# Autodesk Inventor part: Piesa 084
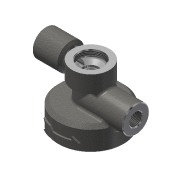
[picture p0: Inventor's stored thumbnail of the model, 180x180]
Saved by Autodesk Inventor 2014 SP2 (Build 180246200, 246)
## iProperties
Created: 2009-02
Part Number: Piesa 084
Document SubType Name: Modeling
Designer: Costel
Material: Steel, Cast
Density: 7.85 g/cm^3
Appearance: Steel - Cast
Mass: 1219.17 g
Surface Area: 379.05 cm^2
Volume: 155.308 cm^3
Author: Costel
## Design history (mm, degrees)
sketch "Sketch2"
  geometry: L1 (42.9, 0)-(-11.7, 0) reference; L2 (0, -6.9)-(0, 89.7) reference; L3 (39, 0)-(39, 24); L4 (35, 28)-(16, 28); L5 (16, 28)-(16, 49); L6 (22, 69)-(0, 69); L7 (0, 69)-(0, 0); L8 (0, 0)-(39, 0); L9 (35, 28)-(39, 24); L10 (16, 49)-(22, 49); L11 (22, 49)-(22, 69); 1 further point
  constraints: 18 end point, 6 point on line, 3 parallel, 3 perpendicular
  dimensions: "d0" = 4 distance of L4.start point (39, 28); "d1" = 4 distance of L3.end point (39, 28) (= d0); "d2" = 69 distance between parallel lines of L8 L6; "d3" = 78 diameter of L3 L2; "d4" = 28 distance between parallel lines of L8 L4; "d5" = 32 diameter of L5 L2; "d6" = 44 diameter of L11 L2; "d7" = 20 distance of L10.end L6.start
revolve "Revolution1" sketch "Sketch2" stored, may be unused: angle "d8" = 90 deg
workplane "Work Plane1"
sketch "Sketch3"
  geometry: L1 (0, -6.9)-(0, 89.7) reference; L2 (-46.8, 0)-(62.4, 0) reference; L3 (-22, 69)-(22, 69) reference; C1 r 16 at (0, 34)
  constraints: 1 centre point, 1 point on line
  dimensions: "d10" = 35 distance from line of L3 C1.centre; "d11" = 32 diameter of C1
extrude "Extrusion1" join sketch "Sketch3" stored distance "d12" = 10; taper "d13" = 0 deg
workaxis "Work Axis1"
sketch "Sketch4"
  geometry: L1 (-81.9, 34)-(48.3, 34) reference; L2 (0, -6.9)-(0, 89.7) reference; L3 (54, 76)-(24, 76); L4 (22, 72.536)-(22, 71); L5 (0, 60)-(54, 60); L6 (54, 60)-(54, 76); L7 (0, 71)-(22, 71); L8 (0, 60)-(0, 71); L9 (24, 76)-(22, 72.536)
  constraints: 14 end point, 2 horizontal, 2 parallel, 1 perpendicular, 1 point on line
  dimensions: "d14" = 26 distance between parallel lines of L1 L5; "d15" = 32 diameter of L3 L5; "d16" = 54 distance between parallel lines of L2 L6; "d18" = 22 diameter of L7 L5; "d20" = 32 distance between parallel lines of L6 L4; "d21" = 2 horizontal distance of L3.end L4.start; "d22" = 30 deg angle of L4 L9
revolve "Revolution2" sketch "Sketch4" stored, may be unused: angle "d19" = 90 deg
chamfer "Chamfer1" distance "d23" = 1.5; stored, may be unused: second distance "d24" = 2, angle "d25" = 45 deg
chamfer "Chamfer2" distance "d26" = 1; stored, may be unused: second distance "d27" = 2, angle "d28" = 45 deg
sketch "Sketch5"
  geometry: L1 (24, 76)-(53, 76) reference; L2 (0, -7.5)-(0, 97.5) reference; L3 (64.8, 0)-(-86.4, 0) reference; L4 (-22, 69)-(21.071, 69) reference; L5 (14.19, 69)-(22, 69); L6 (22, 69)-(22, 76); L7 (22, 76)-(0, 76); L8 (22, 47.464)-(22, 72.536) reference; L9 (14.19, 69)-(14.19, 63); L10 (15, 61)-(15, 63); L11 (15, 63)-(14.19, 63); L12 (13, 61)-(9, 57); L13 (9, 57)-(9, 54.5); L14 (9, 54.5)-(3, 54.5); L15 (3, 54.5)-(3, 15.2); L16 (3, 15.2)-(11, 15.2); L17 (11, 15.2)-(16, 21); L18 (16, 21)-(27.5, 21); L19 (27.5, 21)-(27.5, 14.5); L20 (27.5, 14.5)-(30, 14.5); L21 (30, 14.5)-(30, 9); L22 (30, 9)-(32, 9); L23 (32, 9)-(32, 7); L24 (32, 7)-(31.19, 7); L25 (31.19, 7)-(31.19, 0); L26 (31.19, 0)-(0, 0); L27 (0, 76)-(0, 0); L28 (15, 61)-(13, 61)
  constraints: 46 end point, 8 parallel, 6 perpendicular, 3 collinear, 3 point on line, 1 horizontal, 1 vertical
  dimensions: "d29" = 44 diameter of L6 L2; "d30" = 28.38 diameter of L9 L2; "d31" = 30 diameter of L10 L2; "d32" = 8 distance between parallel lines of L4 L28; "d33" = 2 distance of L10.start L10.end; "d34" = 6 diameter of L15 L2; "d35" = 45 deg angle of L2 L12; "d36" = 18 diameter of L13 L2; "d37" = 2.5 distance of L12.end L13.end; "d38" = 12 distance from line of L4 L12.end; "d39" = 21 distance between parallel lines of L3 L18; "d40" = 0.7 distance between parallel lines of L16 L20; "d41" = 14.5 distance between parallel lines of L3 L20; "d42" = 32 diameter of L17.end L2; "d43" = 22 diameter of L16.end L2; "d44" = 60 diameter of L21 L2; "d45" = 55 diameter of L19 L2; "d46" = 64 diameter of L23 L2; "d47" = 62.38 diameter of L25 L2; "d48" = 9 distance between parallel lines of L3 L22; "d49" = 2 distance of L22.end L23.end
revolve "Revolution3" sketch "Sketch5" stored, may be unused: angle "d55" = 90 deg
hole "Hole1" diameter "d58" = 15; stored, may be unused: countersink angle "d62" = 90 deg, drill point angle "d64" = 118 deg; dims "d56" = 10, "d57" = 10, "d59" = 6, "d60" = 4, "d61" = 2, "d63" = 42
workaxis "Work Axis2"
hole "Hole2" diameter "d67" = 14.95; stored, may be unused: countersink angle "d71" = 90 deg, drill point angle "d73" = 118 deg; dims "d68" = 6, "d69" = 4, "d70" = 2, "d72" = 22, "d124" = 10, "d125" = 10
hole "Hole3" diameter "d76" = 14.95; stored, may be unused: countersink angle "d80" = 90 deg, drill point angle "d82" = 118 deg; dims "d77" = 6, "d78" = 4, "d79" = 2, "d81" = 22, "d126" = 10, "d127" = 10
sketch "Sketch6"
  geometry: L1 (-32, 41.475)-(-32, 26.525) reference; L2 (-81.9, 34)-(48.3, 34) reference; L3 (-34, 34)-(-34, 42.5); L4 (-34, 42.5)-(-32, 42.5); L5 (-32, 42.5)-(-32, 37); L6 (-34, 34)-(0, 34); L7 (0, 34)-(0, 37); L8 (0, 37)-(-32, 37); L9 (0, -7.5)-(0, 97.5) reference; L10 (-54, 26.525)-(-54, 41.475) reference; L11 (-54, 19)-(-54, 49) reference
  constraints: 12 end point, 3 collinear, 2 parallel, 1 horizontal, 1 perpendicular
  dimensions: "d83" = 2 distance of L3.end L4.end; "d84" = 17 diameter of L4 L2; "d85" = 6 diameter of L8 L2
revolve "Revolution4" sketch "Sketch6" stored, may be unused: angle "d86" = 90 deg
sketch "Sketch7"
  geometry: L1 (-86.4, 60)-(64.8, 60) reference; L2 (32, 52.525)-(32, 67.475) reference; L3 (0, -7.5)-(0, 97.5) reference; L4 (32, 63)-(32, 68.5); L5 (32, 68.5)-(34, 68.5); L6 (34, 68.5)-(34, 60); L7 (32, 63)-(0, 63); L8 (0, 63)-(0, 60); L9 (34, 60)-(0, 60); L10 (21.071, 69)-(21.071, 69) reference; L11 (21.071, 69)-(21.071, 69) reference; L12 (14.19, 69)-(-14.19, 69) reference
  constraints: 12 end point, 3 collinear, 1 horizontal, 1 parallel, 1 perpendicular, 1 point on line
  dimensions: "d87" = 17 diameter of L5 L1; "d88" = 2 distance of L4.end L5.end; "d89" = 6 diameter of L7 L1
revolve "Revolution5" sketch "Sketch7" stored, may be unused: angle "d90" = 90 deg
chamfer "Chamfer3" distance "d91" = 1; stored, may be unused: second distance "d92" = 2, angle "d93" = 45 deg
chamfer "Chamfer4" distance "d94" = 1; stored, may be unused: second distance "d95" = 2, angle "d96" = 45 deg
workplane "Work Plane2"
sketch "Sketch8"
  geometry: L1 (0, -7.5)-(0, 97.5) reference; L2 (64.8, 0)-(-86.4, 0) reference; L3 (15, 10)-(-21, 10); L4 (15, 10)-(21, 16); L5 (21, 16)-(9, 16); L6 (9, 16)-(5, 12); L7 (5, 12)-(-15, 12); L8 (-15, 12)-(-15, 16); L9 (-15, 16)-(-21, 10); L10 (-15, 4)-(-21, 10); L11 (-15, 8)-(-15, 4); L12 (5, 8)-(-15, 8); L13 (9, 4)-(5, 8); L14 (21, 4)-(9, 4); L15 (15, 10)-(21, 4)
  constraints: 26 end point, 5 parallel, 5 symmetric about line, 1 perpendicular, 1 point on line
  dimensions: "d98" = 10 distance between parallel lines of L2 L3; "d99" = 90 deg angle of L10 L9; "d100" = 12 distance between parallel lines of L14 L5; "d101" = 4 distance between parallel lines of L12 L7; "d102" = 12 distance of L14.start L13.start; "d103" = 42 horizontal distance of L3.end L14.start; "d104" = 21 distance from line of L1 L3.end
extrude "Extrusion2" join sketch "Sketch8" stored distance "d105" = 10; taper "d106" = 0 deg
sketch "Sketch9"
  geometry: L1 (-53, 18)-(-39, 18) reference; L2 (64.8, 0)-(-86.4, 0) reference; L3 (-54, 19)-(-54, 49) reference; L4 (-53.821, 0)-(-41, 0); L5 (-41, 0)-(-41, 18); L6 (-41, 18)-(-53.821, 18); L7 (-53.821, 18)-(-53.821, 0); L8 (0, -7.5)-(0, 97.5) reference
  constraints: 8 end point, 2 parallel, 2 point on line, 1 horizontal, 1 perpendicular
  dimensions: "d107" = 41 distance between parallel lines of L5 L8
revolve "Revolution6" sketch "Sketch9" stored, may be unused: angle "d108" = 90 deg
sketch "Sketch10"
  geometry: L1 (75.6, 0)-(-75.6, 0) reference; C1 r 16 at (0, 0) reference; 1 further point
  constraints: 1 point on line
  dimensions: "d109" = 23 distance of C1.centre point (-23, 0)
hole "Hole4" sketch "Sketch10" at (-23, 0) diameter "d110" = 3; stored, may be unused: countersink angle "d114" = 90 deg, drill point angle "d116" = 118 deg; dims "d111" = 6, "d112" = 4, "d113" = 2, "d115" = 22
fillet "Fillet1" dims "d119" = 3
thread "Thread1" dims "d120" = 10, "d121" = 0
thread "Thread2" dims "d122" = 10, "d123" = 0
body "Solid1"
node "Projected Loop1"
node "Projected Loop2"
node "Projected Loop3"
other parameters: "d9" = 54, "d97" = -41
